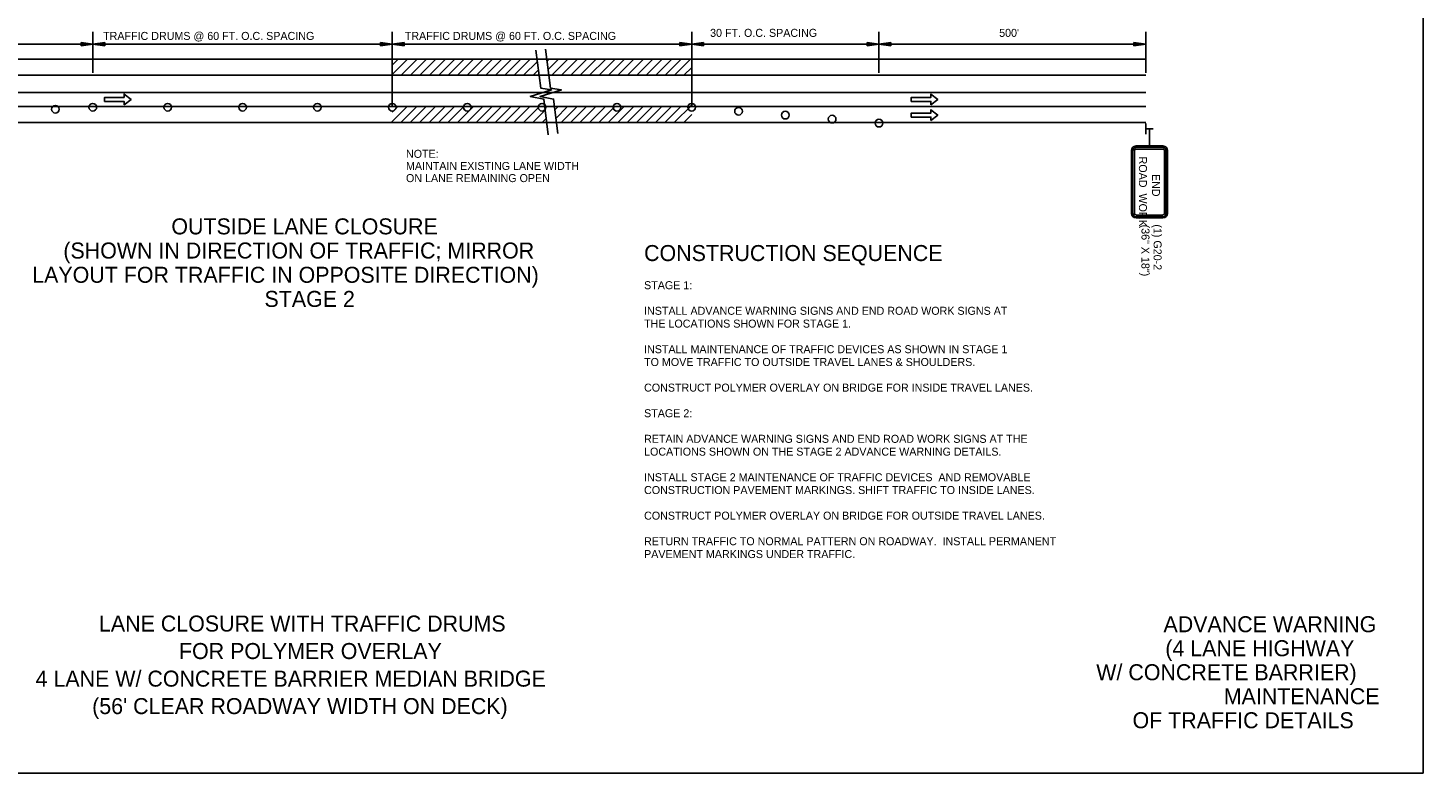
# Model space of a CAD drawing. Extents: x 1930579 to 1938013, y 596452 to 597673.
# Drawn here: x 1936967 to 1938013, y 596573 to 597132 of the extents above; entities that cross this region are included whole.
import ezdxf

# ---------------------------------------------------------------- set-up
doc = ezdxf.new("R2010")
doc.units = 0
for name, color, linetype in [('Default', 7, 'Continuous'), ('P_TC_Signs_Temporary', 7, 'Continuous'), ('R_Annotation', 7, 'Continuous'), ('R_Border', 7, 'Continuous'), ('R_Striping', 7, 'Continuous')]:
    doc.layers.add(name, color=color, linetype=linetype)

msp = doc.modelspace()

# ---------------------------------------------------------------- linework, layer by layer
at = {"layer": 'Default'}
for p, q in [((1937015.5, 597129.2), (1937015.5, 597098.5)), ((1937240, 597129.2), (1937240, 597073.1)), ((1937464.5, 597129.2), (1937464.5, 597073.1)), ((1937604.9, 597129.2), (1937604.9, 597098.5)), ((1937804.9, 597129.2), (1937804.9, 597098.5)), ((1937015.5, 597119.9), (1936791, 597119.9)), ((1937015.5, 597119.9), (1937006.7, 597121.2)), ((1937006.7, 597121.2), (1937006.7, 597118.6)), ((1937006.7, 597118.6), (1937015.5, 597119.9)), ((1937015.5, 597119.9), (1937024.4, 597121.2)), ((1937240, 597119.9), (1937015.5, 597119.9)), ((1937024.4, 597118.6), (1937015.5, 597119.9)), ((1937024.4, 597121.2), (1937024.4, 597118.6)), ((1937231.2, 597118.6), (1937231.2, 597121.2)), ((1937231.2, 597121.2), (1937240, 597119.9)), ((1937240, 597119.9), (1937231.2, 597118.6)), ((1937248.9, 597121.2), (1937240, 597119.9)), ((1937464.5, 597119.9), (1937240, 597119.9)), ((1937240, 597119.9), (1937248.9, 597118.6)), ((1937248.9, 597118.6), (1937248.9, 597121.2)), ((1937455.7, 597118.6), (1937455.7, 597121.2)), ((1937455.7, 597121.2), (1937464.5, 597119.9)), ((1937464.5, 597119.9), (1937455.7, 597118.6)), ((1937473.4, 597121.2), (1937464.5, 597119.9)), ((1937604.9, 597119.9), (1937464.5, 597119.9)), ((1937464.5, 597119.9), (1937473.4, 597118.6)), ((1937473.4, 597118.6), (1937473.4, 597121.2)), ((1937596, 597118.6), (1937596, 597121.2)), ((1937596, 597121.2), (1937604.9, 597119.9)), ((1937604.9, 597119.9), (1937596, 597118.6)), ((1937613.7, 597121.2), (1937604.9, 597119.9)), ((1937804.9, 597119.9), (1937604.9, 597119.9)), ((1937604.9, 597119.9), (1937613.7, 597118.6)), ((1937613.7, 597118.6), (1937613.7, 597121.2)), ((1937796, 597118.6), (1937796, 597121.2)), ((1937796, 597121.2), (1937804.9, 597119.9)), ((1937804.9, 597119.9), (1937796, 597118.6)), ((1937804.9, 597108.7), (1936452.7, 597108.7)), ((1937240, 597097.2), (1937251.5, 597108.7)), ((1937240, 597104.2), (1937244.5, 597108.7)), ((1937246.6, 597096.7), (1937258.6, 597108.7)), ((1937253.7, 597096.7), (1937265.7, 597108.7)), ((1937260.7, 597096.7), (1937272.7, 597108.7)), ((1937267.8, 597096.7), (1937279.8, 597108.7)), ((1937274.9, 597096.7), (1937286.9, 597108.7)), ((1937282, 597096.7), (1937294, 597108.7)), ((1937289, 597096.7), (1937301, 597108.7)), ((1937296.1, 597096.7), (1937308.1, 597108.7)), ((1937303.2, 597096.7), (1937315.2, 597108.7)), ((1937310.2, 597096.7), (1937322.2, 597108.7)), ((1937317.3, 597096.7), (1937329.3, 597108.7)), ((1937324.4, 597096.7), (1937336.4, 597108.7)), ((1937331.5, 597096.7), (1937343.5, 597108.7)), ((1937338.5, 597096.7), (1937348.8, 597106.9)), ((1937356.1, 597107.1), (1937357.6, 597108.7)), ((1937356.8, 597100.8), (1937364.7, 597108.7)), ((1937359.7, 597096.7), (1937371.7, 597108.7)), ((1937366.8, 597096.7), (1937378.8, 597108.7)), ((1937373.9, 597096.7), (1937385.9, 597108.7)), ((1937380.9, 597096.7), (1937392.9, 597108.7)), ((1937388, 597096.7), (1937400, 597108.7)), ((1937395.1, 597096.7), (1937407.1, 597108.7)), ((1937402.2, 597096.7), (1937414.2, 597108.7)), ((1937409.2, 597096.7), (1937421.2, 597108.7)), ((1937416.3, 597096.7), (1937428.3, 597108.7)), ((1937423.4, 597096.7), (1937435.4, 597108.7)), ((1937430.4, 597096.7), (1937442.4, 597108.7)), ((1937437.5, 597096.7), (1937449.5, 597108.7)), ((1937444.6, 597096.7), (1937456.6, 597108.7)), ((1937451.7, 597096.7), (1937463.7, 597108.7)), ((1937458.7, 597096.7), (1937464.5, 597102.5)), ((1937804.9, 597096.7), (1936452.7, 597096.7)), ((1937345.6, 597096.7), (1937349.6, 597100.6)), ((1937804.9, 597083.8), (1936452.7, 597083.8)), ((1937350.9, 597080.7), (1937350.9, 597080.7)), ((1937804.9, 597073.1), (1936452.7, 597073.1)), ((1937239.3, 597061.1), (1937251.3, 597073.1)), ((1937240, 597068.9), (1937244.2, 597073.1)), ((1937246.4, 597061.1), (1937258.4, 597073.1)), ((1937253.5, 597061.1), (1937265.5, 597073.1)), ((1937260.5, 597061.1), (1937272.5, 597073.1)), ((1937267.6, 597061.1), (1937279.6, 597073.1)), ((1937274.7, 597061.1), (1937286.7, 597073.1)), ((1937281.7, 597061.1), (1937293.7, 597073.1)), ((1937288.8, 597061.1), (1937300.8, 597073.1)), ((1937295.9, 597061.1), (1937307.9, 597073.1)), ((1937303, 597061.1), (1937315, 597073.1)), ((1937310, 597061.1), (1937322, 597073.1)), ((1937317.1, 597061.1), (1937329.1, 597073.1)), ((1937324.2, 597061.1), (1937336.2, 597073.1)), ((1937331.2, 597061.1), (1937343.2, 597073.1)), ((1937338.3, 597061.1), (1937350.3, 597073.1)), ((1937345.4, 597061.1), (1937354.7, 597070.4)), ((1937362, 597070.6), (1937364.5, 597073.1)), ((1937362.7, 597064.3), (1937371.5, 597073.1)), ((1937366.6, 597061.1), (1937378.6, 597073.1)), ((1937373.7, 597061.1), (1937385.7, 597073.1)), ((1937380.7, 597061.1), (1937392.7, 597073.1)), ((1937387.8, 597061.1), (1937399.8, 597073.1)), ((1937394.9, 597061.1), (1937406.9, 597073.1)), ((1937401.9, 597061.1), (1937413.9, 597073.1)), ((1937409, 597061.1), (1937421, 597073.1)), ((1937416.1, 597061.1), (1937428.1, 597073.1)), ((1937423.2, 597061.1), (1937435.2, 597073.1)), ((1937430.2, 597061.1), (1937442.2, 597073.1)), ((1937437.3, 597061.1), (1937449.3, 597073.1)), ((1937444.4, 597061.1), (1937456.4, 597073.1)), ((1937451.4, 597061.1), (1937464.5, 597074.2)), ((1937463.4, 597073.1), (1937464.5, 597074.2)), ((1937804.9, 597061.1), (1936452.7, 597061.1)), ((1937352.5, 597061.1), (1937355.5, 597064.1)), ((1937458.5, 597061.1), (1937464.5, 597067.1)), ((1937804.9, 597052.4), (1937804.9, 597060.4)), ((1937805, 597056.4), (1937810.4, 597056.4))]:
    msp.add_line(p, q, dxfattribs=at)
for points in [[(1937347.7, 597115.3), (1937351.3, 597087), (1937359.5, 597085.6), (1937343.5, 597080.7), (1937353.7, 597078.8), (1937356.9, 597052)], [(1937354.9, 597116.2), (1937358.6, 597087), (1937366.8, 597085.6), (1937350.8, 597080.7), (1937361, 597078.8), (1937364.1, 597052.9)]]:
    msp.add_lwpolyline(points, dxfattribs=at)
for centre in [(1936987.5, 597071.1), (1937015.5, 597072.6), (1937071.7, 597072.6), (1937127.8, 597072.6), (1937183.9, 597072.6), (1937240, 597072.6), (1937296.2, 597072.6), (1937352.3, 597072.6), (1937408.4, 597072.6), (1937464.5, 597072.6), (1937499.6, 597069.6), (1937534.7, 597066.7), (1937569.8, 597063.7), (1937604.9, 597060.7)]:
    msp.add_circle(centre, 2.87, dxfattribs=at)
at = {"layer": 'P_TC_Signs_Temporary'}
for p, q in [((1937794.2, 597040.2), (1937794.2, 596993)), ((1937795.1, 597040.2), (1937795.1, 596993)), ((1937796.5, 597040.2), (1937796.5, 596993)), ((1937817.8, 597043.6), (1937797.6, 597043.6)), ((1937817.8, 597042.7), (1937797.6, 597042.7)), ((1937817.8, 597041.3), (1937797.6, 597041.3)), ((1937819, 596993), (1937819, 597040.2)), ((1937820.3, 596993), (1937820.3, 597040.2)), ((1937821.2, 596993), (1937821.2, 597040.2)), ((1937797.6, 596991.8), (1937817.8, 596991.8)), ((1937797.6, 596990.5), (1937817.8, 596990.5)), ((1937797.6, 596989.6), (1937817.8, 596989.6))]:
    msp.add_line(p, q, dxfattribs=at)
for centre, radius, start, end in [((1937797.6, 597040.2), 3.38, 90, 180), ((1937797.6, 597040.2), 2.44, 90, 180), ((1937797.6, 597040.2), 1.13, 90, 180), ((1937817.8, 597040.2), 3.37, 360, 90), ((1937817.8, 597040.2), 2.44, 360, 90), ((1937817.8, 597040.2), 1.13, 360, 90), ((1937797.6, 596993), 3.37, 180, 270), ((1937797.6, 596993), 2.44, 180, 270), ((1937797.6, 596993), 1.13, 180, 270), ((1937817.8, 596993), 2.44, 270, 360), ((1937817.8, 596993), 1.13, 270, 360), ((1937817.8, 596993), 3.38, 270, 360)]:
    msp.add_arc(centre, radius, start, end, dxfattribs=at)
at = {"layer": 'R_Annotation'}
msp.add_line((1937807.7, 597056.4), (1937807.7, 597043.6), dxfattribs=at)
at = {"layer": 'R_Border'}
msp.add_lwpolyline([(1938012.8, 597673.4), (1936312.8, 597673.4), (1936312.8, 596573.4), (1938012.8, 596573.4)], close=True, dxfattribs=at)
at = {"layer": 'R_Striping'}
for points in [[(1937039, 597074.5), (1937044.2, 597078.5), (1937039, 597082.5), (1937039, 597080), (1937024.3, 597080), (1937024.3, 597077), (1937039, 597077)], [(1937643.8, 597074.5), (1937649, 597078.5), (1937643.8, 597082.5), (1937643.8, 597080), (1937629.1, 597080), (1937629.1, 597077), (1937643.8, 597077)], [(1937643.8, 597062.7), (1937649, 597066.7), (1937643.8, 597070.7), (1937643.8, 597068.2), (1937629.1, 597068.2), (1937629.1, 597065.2), (1937643.8, 597065.2)]]:
    msp.add_lwpolyline(points, close=True, dxfattribs=at)

# ---------------------------------------------------------------- texts
at = {"layer": 'Default'}
for s, height, p in [('TRAFFIC DRUMS @ 60 FT. O.C. SPACING', 6, (1937023.2, 597123.1)), ('TRAFFIC DRUMS @ 60 FT. O.C. SPACING', 6, (1937249.4, 597123.1)), ('30 FT. O.C. SPACING', 6, (1937478.3, 597125.4)), ("500'", 6, (1937695, 597125.4)), ('OUTSIDE LANE CLOSURE', 12, (1937074.4, 596977.3)), ('(SHOWN IN DIRECTION OF TRAFFIC; MIRROR', 12, (1936993.4, 596959.2)), (' LAYOUT FOR TRAFFIC IN OPPOSITE DIRECTION)', 12, (1936965.6, 596941)), ('STAGE 2', 12, (1937144.2, 596922.9)), ('LANE CLOSURE WITH TRAFFIC DRUMS', 12, (1937020.1, 596679.5)), ('FOR POLYMER OVERLAY', 12, (1937080.1, 596658.9)), ('4 LANE W/ CONCRETE BARRIER MEDIAN BRIDGE', 12, (1936972.6, 596638.2)), ("(56' CLEAR ROADWAY WIDTH ON DECK)", 12, (1937015, 596617.6))]:
    msp.add_text(s, height=height, rotation=360, dxfattribs=at).set_placement(p)
at = {"layer": 'P_TC_Signs_Temporary'}
for s, p in [('ROAD  WORK', (1937799.8, 597035.6)), ('END', (1937809.6, 597022.6))]:
    msp.add_text(s, height=6, rotation=270, dxfattribs=at).set_placement(p)
at = {"layer": 'R_Annotation'}
for s, height, rotation, p in [('NOTE:', 6, 360, (1937250.3, 597034.7)), ('MAINTAIN EXISTING LANE WIDTH', 6, 360, (1937250.3, 597025.6)), ('ON LANE REMAINING OPEN', 6, 360, (1937250.3, 597016.5)), ('(36" X 18")', 6, 270, (1937801.7, 596984.6)), ('(1) G20-2', 6, 270, (1937810.8, 596984.8)), ('CONSTRUCTION SEQUENCE', 12, 360, (1937428.8, 596957.3)), ('STAGE 1:', 6, 360, (1937428.8, 596936.2)), ('THE LOCATIONS SHOWN FOR STAGE 1.', 6, 360, (1937428.8, 596907.4)), ('INSTALL ADVANCE WARNING SIGNS AND END ROAD WORK SIGNS AT', 6, 360, (1937428.8, 596917)), ('INSTALL MAINTENANCE OF TRAFFIC DEVICES AS SHOWN IN STAGE 1', 6, 360, (1937428.8, 596888.2)), ('TO MOVE TRAFFIC TO OUTSIDE TRAVEL LANES & SHOULDERS.', 6, 360, (1937428.8, 596878.6)), ('CONSTRUCT POLYMER OVERLAY ON BRIDGE FOR INSIDE TRAVEL LANES.', 6, 360, (1937428.8, 596859.4)), ('STAGE 2:', 6, 360, (1937428.8, 596840.2)), ('RETAIN ADVANCE WARNING SIGNS AND END ROAD WORK SIGNS AT THE', 6, 360, (1937428.8, 596821)), ('LOCATIONS SHOWN ON THE STAGE 2 ADVANCE WARNING DETAILS.', 6, 360, (1937428.8, 596811.4)), ('INSTALL STAGE 2 MAINTENANCE OF TRAFFIC DEVICES  AND REMOVABLE', 6, 360, (1937428.8, 596792.2)), ('CONSTRUCTION PAVEMENT MARKINGS. SHIFT TRAFFIC TO INSIDE LANES.', 6, 360, (1937428.8, 596782.6)), ('CONSTRUCT POLYMER OVERLAY ON BRIDGE FOR OUTSIDE TRAVEL LANES.', 6, 360, (1937428.8, 596763.4)), ('RETURN TRAFFIC TO NORMAL PATTERN ON ROADWAY.  INSTALL PERMANENT', 6, 360, (1937428.8, 596744.2)), ('PAVEMENT MARKINGS UNDER TRAFFIC.', 6, 360, (1937428.8, 596734.6)), ('ADVANCE WARNING', 12, 360, (1937818.2, 596679)), (' (4 LANE HIGHWAY', 12, 360, (1937815.1, 596661)), ('W/ CONCRETE BARRIER)', 12, 360, (1937767.8, 596643)), ('MAINTENANCE ', 12, 360, (1937863.4, 596625)), ('OF TRAFFIC DETAILS', 12, 360, (1937795, 596607))]:
    msp.add_text(s, height=height, rotation=rotation, dxfattribs=at).set_placement(p)

doc.saveas('drawing.dxf')
